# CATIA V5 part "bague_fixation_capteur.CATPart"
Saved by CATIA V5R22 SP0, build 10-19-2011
Part number: bague_fixation_capteur
Bounding box of the stored display mesh (mm): x 0 to 5, y -11.298 to 11.298, z -11.3 to 11.2
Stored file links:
  D:\PER\CAO_PER_MODIF_2025\CAO_PER_pick&place_2024P\Sous_Ensemble_Flacon\bague_fixation_capteur.CATPart
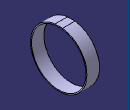
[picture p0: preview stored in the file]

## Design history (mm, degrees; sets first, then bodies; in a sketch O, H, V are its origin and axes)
Body1 (main body)
  Sketch1 on yz-plane, origin (0, 0, 0), H (0, 1, 0), V (0, 0, 1)
    arc A1 centre (0, 0) radius 10.9 from (-1.4731, 10.8) to (1.4731, 10.8) ccw
    point P1 (0.0378, -0.1964)
    line L1 (-1.4731, 10.8) -> (1.4731, 10.8)
    point P4 (2.5104, 5.0617)
    arc A2 centre (0, 0) radius 11.3 from (-1.5, 11.2) to (1.5, 11.2) ccw
    line L2 (1.5, 11.2) -> (-1.5, 11.2)
    radius A1 = 10.9
    distance A1 A2 = 0.4
    distance L1 L2 = 0.4
    distance L1 H = 10.8
    horizontal: L1 H, L2 H
  Pad1: profile Sketch1, direction (1, 0, 0), length 5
